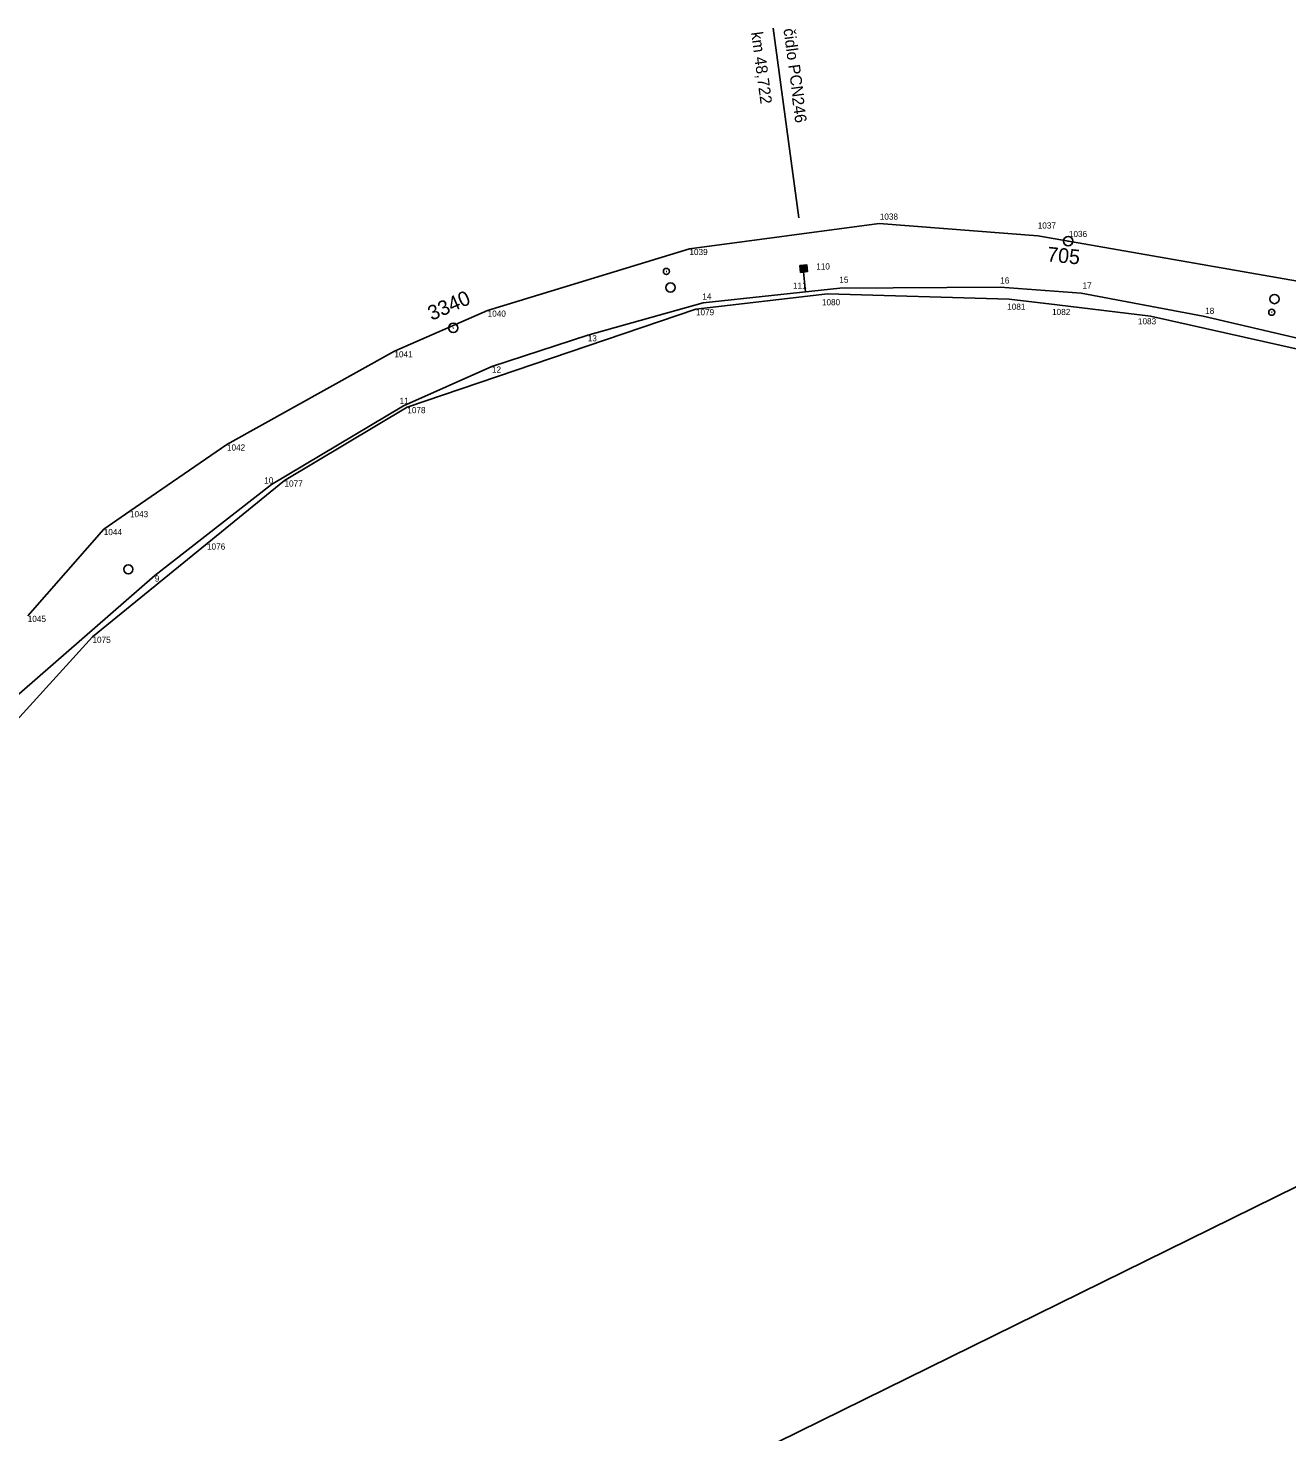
# Model space of a CAD drawing. Extents: x -679938 to -678300, y -1007495 to -1006487.
# Drawn here: x -678917.3 to -678711.9, y -1006995.4 to -1006766.4 of the extents above; entities that cross this region are included whole.
import ezdxf

# ---------------------------------------------------------------- set-up
doc = ezdxf.new("R2010")
doc.units = 0
for name, color, linetype in [('ramy - Sekce lichá', 7, 'Continuous'), ('SSZT nové - lomové body', 7, 'Continuous'), ('SSZT_nové', 7, 'Continuous'), ('Stávající ŽBP', 7, 'Continuous'), ('SŽDC', 7, 'Continuous'), ('SŽDC - body', 7, 'Continuous'), ('Vrstva 7', 7, 'Continuous')]:
    doc.layers.add(name, color=color, linetype=linetype)

msp = doc.modelspace()

# ---------------------------------------------------------------- linework, layer by layer
at = {"layer": 'ramy - Sekce lichá'}
msp.add_line((-678864.85, -1007031.4), (-678676.44, -1006938.65), dxfattribs=at)
at = {"layer": 'SSZT nové - lomové body'}
for p, q in [((-678790.77, -1006806.16), (-678790.77, -1006806.16)), ((-678790.43, -1006809.44), (-678790.43, -1006809.44)), ((-678784.83, -1006808.82), (-678784.83, -1006808.82)), ((-678758.68, -1006808.66), (-678758.68, -1006808.66)), ((-678745.48, -1006809.62), (-678745.48, -1006809.62)), ((-678807.13, -1006811.25), (-678807.13, -1006811.25)), ((-678725.58, -1006813.41), (-678725.58, -1006813.41)), ((-678825.98, -1006816.5), (-678825.98, -1006816.5)), ((-678841.61, -1006821.61), (-678841.61, -1006821.61)), ((-678856.04, -1006828.01), (-678856.04, -1006828.01)), ((-678877.58, -1006840.85), (-678877.58, -1006840.85)), ((-678896.62, -1006855.69), (-678896.62, -1006855.69))]:
    msp.add_line(p, q, dxfattribs=at)
at = {"layer": 'SSZT_nové'}
for p, q in [((-678795.74, -1006766.41), (-678791.54, -1006797.36)), ((-678791.35, -1006805.36), (-678791.15, -1006805.11)), ((-678791.32, -1006805.66), (-678790.85, -1006805.08)), ((-678791.29, -1006805.96), (-678790.55, -1006805.04)), ((-678791.25, -1006806.26), (-678790.25, -1006805.01)), ((-678790.96, -1006806.23), (-678790.22, -1006805.31)), ((-678790.66, -1006806.19), (-678790.19, -1006805.61)), ((-678790.36, -1006806.16), (-678790.15, -1006805.91)), ((-678790.77, -1006806.16), (-678790.43, -1006809.44))]:
    msp.add_line(p, q, dxfattribs=at)
for points in [[(-678758.68, -1006808.66), (-678745.48, -1006809.62), (-678725.58, -1006813.41), (-678679.95, -1006824.06), (-678653.68, -1006829.31), (-678623.86, -1006830.09), (-678598.34, -1006831.32), (-678578.56, -1006827.33), (-678548.42, -1006815.94), (-678538.41, -1006812.42), (-678518.43, -1006801.56), (-678512.32, -1006796.58)], [(-678982.82, -1006929.34), (-678948.72, -1006900.67), (-678932.41, -1006886.82), (-678896.62, -1006855.69), (-678877.58, -1006840.85), (-678856.04, -1006828.01), (-678841.61, -1006821.61), (-678825.98, -1006816.5), (-678807.13, -1006811.25), (-678784.83, -1006808.82), (-678758.68, -1006808.66)]]:
    msp.add_lwpolyline(points, dxfattribs=at)
msp.add_lwpolyline([(-678791.38, -1006805.13), (-678790.25, -1006805.01), (-678790.13, -1006806.14), (-678791.25, -1006806.26)], close=True, dxfattribs=at)
at = {"layer": 'Stávající ŽBP'}
for p, q in [((-678747.64, -1006801.15), (-678747.54, -1006801.15)), ((-678847.97, -1006815.33), (-678847.88, -1006815.29))]:
    msp.add_line(p, q, dxfattribs=at)
for centre in [(-678747.59, -1006801.15), (-678847.92, -1006815.31)]:
    msp.add_circle(centre, 0.756, dxfattribs=at)
at = {"layer": 'SŽDC'}
for p, q in [((-678778.41, -1006798.31), (-678809.39, -1006802.43)), ((-678752.56, -1006800.28), (-678778.41, -1006798.31)), ((-678748.44, -1006800.99), (-678752.56, -1006800.28)), ((-678681.43, -1006812.76), (-678748.44, -1006800.99)), ((-678809.39, -1006802.43), (-678842.31, -1006812.48)), ((-678808.33, -1006812.25), (-678786.87, -1006809.74)), ((-678786.87, -1006809.74), (-678757.2, -1006810.62)), ((-678757.2, -1006810.62), (-678749.38, -1006811.56)), ((-678842.31, -1006812.48), (-678857.52, -1006819.11)), ((-678855.42, -1006828.22), (-678808.33, -1006812.25)), ((-678749.38, -1006811.56), (-678734.16, -1006813.39)), ((-678734.16, -1006813.39), (-678693.35, -1006822.57)), ((-678857.52, -1006819.11), (-678884.85, -1006834.32)), ((-678875.46, -1006840.19), (-678855.42, -1006828.22)), ((-678884.85, -1006834.32), (-678900.68, -1006845.18)), ((-678888.1, -1006850.47), (-678875.46, -1006840.19)), ((-678900.68, -1006845.18), (-678904.95, -1006848.11)), ((-678904.95, -1006848.11), (-678917.35, -1006862.27)), ((-678906.79, -1006865.68), (-678888.1, -1006850.47)), ((-678937.15, -1006899.06), (-678906.79, -1006865.68))]:
    msp.add_line(p, q, dxfattribs=at)
at = {"layer": 'SŽDC - body'}
for p, q in [((-678778.41, -1006798.31), (-678778.41, -1006798.31)), ((-678752.56, -1006800.28), (-678752.56, -1006800.28)), ((-678748.44, -1006800.99), (-678748.44, -1006800.99)), ((-678809.39, -1006802.43), (-678809.39, -1006802.43)), ((-678786.87, -1006809.74), (-678786.87, -1006809.74)), ((-678757.2, -1006810.62), (-678757.2, -1006810.62)), ((-678842.31, -1006812.48), (-678842.31, -1006812.48)), ((-678808.33, -1006812.25), (-678808.33, -1006812.25)), ((-678749.38, -1006811.56), (-678749.38, -1006811.56)), ((-678734.16, -1006813.39), (-678734.16, -1006813.39)), ((-678857.52, -1006819.11), (-678857.52, -1006819.11)), ((-678855.42, -1006828.22), (-678855.42, -1006828.22)), ((-678884.85, -1006834.32), (-678884.85, -1006834.32)), ((-678875.46, -1006840.19), (-678875.46, -1006840.19)), ((-678900.68, -1006845.18), (-678900.68, -1006845.18)), ((-678904.95, -1006848.11), (-678904.95, -1006848.11)), ((-678888.1, -1006850.47), (-678888.1, -1006850.47)), ((-678906.79, -1006865.68), (-678906.79, -1006865.68))]:
    msp.add_line(p, q, dxfattribs=at)
at = {"layer": 'Vrstva 7'}
for p, q in [((-678813.19, -1006806.13), (-678813.09, -1006806.1)), ((-678714.42, -1006812.75), (-678714.32, -1006812.77))]:
    msp.add_line(p, q, dxfattribs=at)
for centre, radius in [((-678813.14, -1006806.11), 0.5), ((-678812.47, -1006808.72), 0.75), ((-678713.92, -1006810.61), 0.75), ((-678714.37, -1006812.76), 0.5), ((-678900.93, -1006854.68), 0.75)]:
    msp.add_circle(centre, radius, dxfattribs=at)

# ---------------------------------------------------------------- texts
at = {"layer": 'SSZT nové - lomové body'}
for s, p in [('110', (-678788.7, -1006805.79)), ('111', (-678792.5, -1006808.93)), ('15', (-678784.93, -1006807.95)), ('16', (-678758.68, -1006808.07)), ('17', (-678745.25, -1006808.89)), ('14', (-678807.28, -1006810.68)), ('18', (-678725.24, -1006813.03)), ('13', (-678825.98, -1006817.5)), ('12', (-678841.61, -1006822.61)), ('11', (-678856.67, -1006827.71)), ('10', (-678878.77, -1006840.69)), ('9', (-678896.62, -1006856.69))]:
    msp.add_text(s, height=1, dxfattribs=at).set_placement(p)
at = {"layer": 'SSZT_nové'}
for s, p in [('km 48,722', (-678799.34, -1006767.14)), ('čidlo PCN ', (-678794.06, -1006766.57)), ('246', (-678792.66, -1006777.77))]:
    msp.add_text(s, height=1.9, rotation=277.6328, dxfattribs=at).set_placement(p)
at = {"layer": 'Stávající ŽBP'}
for s, rotation, p in [('705', 354.2996, (-678751.11, -1006804.45)), ('3340', 23.602, (-678851.44, -1006814.17))]:
    msp.add_text(s, height=2.4, rotation=rotation, dxfattribs=at).set_placement(p)
at = {"layer": 'SŽDC - body'}
for s, p in [('1038', (-678778.33, -1006797.66)), ('1037', (-678752.56, -1006799.11)), ('1036', (-678747.47, -1006800.49)), ('1039', (-678809.39, -1006803.43)), ('1080', (-678787.77, -1006811.62)), ('1040', (-678842.31, -1006813.48)), ('1079', (-678808.33, -1006813.25)), ('1081', (-678757.54, -1006812.36)), ('1082', (-678750.22, -1006813.21)), ('1083', (-678736.21, -1006814.73)), ('1041', (-678857.52, -1006820.11)), ('1078', (-678855.42, -1006829.22)), ('1042', (-678884.85, -1006835.32)), ('1077', (-678875.46, -1006841.19)), ('1043', (-678900.68, -1006846.18)), ('1044', (-678904.95, -1006849.11)), ('1076', (-678888.1, -1006851.47)), ('1045', (-678917.35, -1006863.27)), ('1075', (-678906.79, -1006866.68))]:
    msp.add_text(s, height=1, dxfattribs=at).set_placement(p)

doc.saveas('drawing.dxf')
